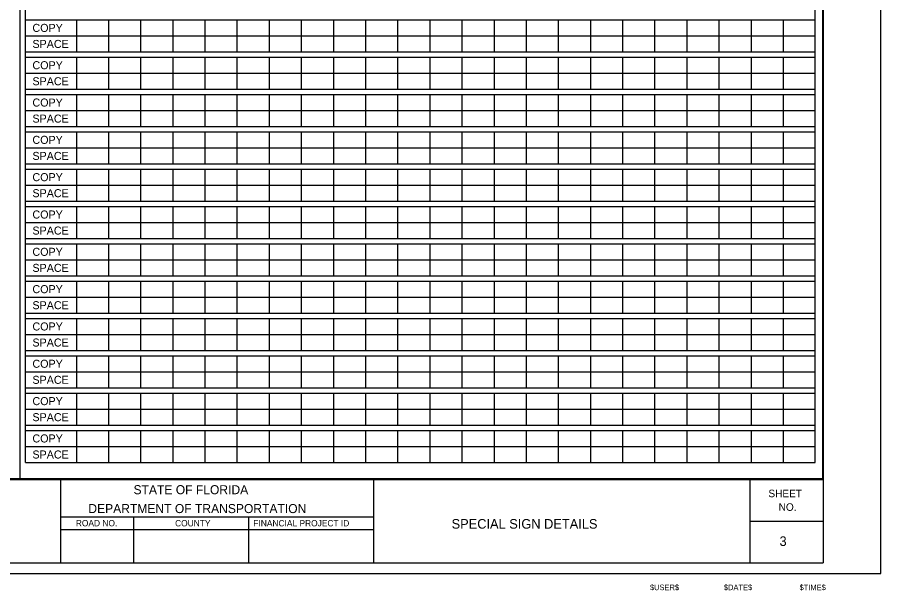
# Model space of a CAD drawing. Extents: x 17890459 to 17890580, y 17897938 to 17898017.
# Drawn here: x 17890519.4 to 17890580, y 17897938.3 to 17897978.6 of the extents above; entities that cross this region are included whole.
import ezdxf

# ---------------------------------------------------------------- set-up
doc = ezdxf.new("R2010")
doc.units = 0
for name, color, linetype in [('PlotBorder_dp', 7, 'Continuous'), ('SheetBorder_dp', 7, 'Continuous'), ('SheetLines_dp', 7, 'Continuous'), ('SheetLinesMisc2_dp', 7, 'Continuous'), ('TextMinor', 7, 'Continuous'), ('TextMisc', 7, 'Continuous')]:
    doc.layers.add(name, color=color, linetype=linetype)

msp = doc.modelspace()

# ---------------------------------------------------------------- linework, layer by layer
at = {"layer": 'PlotBorder_dp'}
msp.add_lwpolyline([(17890458.908, 17897939.544), (17890580.045, 17897939.544), (17890580.045, 17898017.365), (17890458.908, 17898017.365)], close=True, dxfattribs=at)
at = {"layer": 'SheetBorder_dp'}
for p, q in [((17890576.007, 17898016.631), (17890576.007, 17897940.278)), ((17890462.946, 17897946.151), (17890576.007, 17897946.151)), ((17890462.946, 17897940.278), (17890576.007, 17897940.278))]:
    msp.add_line(p, q, dxfattribs=at)
at = {"layer": 'SheetLines_dp'}
for p, q in [((17890522.413, 17897946.151), (17890522.413, 17897940.278)), ((17890544.438, 17897940.278), (17890544.438, 17897946.151)), ((17890570.867, 17897940.278), (17890570.867, 17897946.151)), ((17890522.413, 17897943.508), (17890544.438, 17897943.508)), ((17890527.552, 17897943.508), (17890527.552, 17897940.278)), ((17890535.628, 17897943.508), (17890535.628, 17897940.278)), ((17890570.867, 17897943.215), (17890576.007, 17897943.215)), ((17890522.413, 17897942.627), (17890544.438, 17897942.627))]:
    msp.add_line(p, q, dxfattribs=at)
at = {"layer": 'SheetLinesMisc2_dp'}
for p, q in [((17890519.566, 17898016.456), (17890519.566, 17897946.221)), ((17890575.98, 17897946.221), (17890575.98, 17898016.456)), ((17890519.957, 17897947.331), (17890519.957, 17897991.536)), ((17890575.447, 17897947.331), (17890575.447, 17897991.536)), ((17890519.957, 17897978.426), (17890575.447, 17897978.426)), ((17890523.529, 17897978.426), (17890523.529, 17897976.172)), ((17890525.787, 17897978.426), (17890525.787, 17897976.172)), ((17890528.044, 17897978.426), (17890528.044, 17897976.172)), ((17890530.301, 17897978.426), (17890530.301, 17897976.172)), ((17890532.558, 17897978.426), (17890532.558, 17897976.172)), ((17890534.815, 17897978.426), (17890534.815, 17897976.172)), ((17890537.073, 17897978.426), (17890537.073, 17897976.172)), ((17890539.33, 17897978.426), (17890539.33, 17897976.172)), ((17890541.587, 17897978.426), (17890541.587, 17897976.172)), ((17890543.844, 17897978.426), (17890543.844, 17897976.172)), ((17890546.102, 17897978.426), (17890546.102, 17897976.172)), ((17890548.359, 17897978.426), (17890548.359, 17897976.172)), ((17890550.617, 17897978.426), (17890550.617, 17897976.172)), ((17890552.874, 17897978.426), (17890552.874, 17897976.172)), ((17890555.132, 17897978.426), (17890555.132, 17897976.172)), ((17890557.388, 17897978.426), (17890557.388, 17897976.172)), ((17890559.646, 17897978.426), (17890559.646, 17897976.172)), ((17890561.903, 17897978.426), (17890561.903, 17897976.172)), ((17890564.161, 17897978.426), (17890564.161, 17897976.172)), ((17890566.418, 17897978.426), (17890566.418, 17897976.172)), ((17890568.675, 17897978.426), (17890568.675, 17897976.172)), ((17890570.932, 17897978.426), (17890570.932, 17897976.172)), ((17890573.19, 17897978.426), (17890573.19, 17897976.172)), ((17890519.957, 17897977.299), (17890575.447, 17897977.299)), ((17890519.957, 17897976.172), (17890575.447, 17897976.172)), ((17890519.957, 17897975.804), (17890575.447, 17897975.804)), ((17890523.529, 17897975.804), (17890523.529, 17897973.55)), ((17890525.787, 17897975.804), (17890525.787, 17897973.55)), ((17890528.044, 17897975.804), (17890528.044, 17897973.55)), ((17890530.301, 17897975.804), (17890530.301, 17897973.55)), ((17890532.558, 17897975.804), (17890532.558, 17897973.55)), ((17890534.815, 17897975.804), (17890534.815, 17897973.55)), ((17890537.073, 17897975.804), (17890537.073, 17897973.55)), ((17890539.33, 17897975.804), (17890539.33, 17897973.55)), ((17890541.587, 17897975.804), (17890541.587, 17897973.55)), ((17890543.844, 17897975.804), (17890543.844, 17897973.55)), ((17890546.102, 17897975.804), (17890546.102, 17897973.55)), ((17890548.359, 17897975.804), (17890548.359, 17897973.55)), ((17890550.617, 17897975.804), (17890550.617, 17897973.55)), ((17890552.874, 17897975.804), (17890552.874, 17897973.55)), ((17890555.132, 17897975.804), (17890555.132, 17897973.55)), ((17890557.388, 17897975.804), (17890557.388, 17897973.55)), ((17890559.646, 17897975.804), (17890559.646, 17897973.55)), ((17890561.903, 17897975.804), (17890561.903, 17897973.55)), ((17890564.161, 17897975.804), (17890564.161, 17897973.55)), ((17890566.418, 17897975.804), (17890566.418, 17897973.55)), ((17890568.675, 17897975.804), (17890568.675, 17897973.55)), ((17890570.932, 17897975.804), (17890570.932, 17897973.55)), ((17890573.19, 17897975.804), (17890573.19, 17897973.55)), ((17890519.957, 17897974.677), (17890575.447, 17897974.677)), ((17890519.957, 17897973.55), (17890575.447, 17897973.55)), ((17890519.957, 17897973.182), (17890575.447, 17897973.182)), ((17890523.529, 17897973.182), (17890523.529, 17897970.928)), ((17890525.787, 17897973.182), (17890525.787, 17897970.928)), ((17890528.044, 17897973.182), (17890528.044, 17897970.928)), ((17890530.301, 17897973.182), (17890530.301, 17897970.928)), ((17890532.558, 17897973.182), (17890532.558, 17897970.928)), ((17890534.815, 17897973.182), (17890534.815, 17897970.928)), ((17890537.073, 17897973.182), (17890537.073, 17897970.928)), ((17890539.33, 17897973.182), (17890539.33, 17897970.928)), ((17890541.587, 17897973.182), (17890541.587, 17897970.928)), ((17890543.844, 17897973.182), (17890543.844, 17897970.928)), ((17890546.102, 17897973.182), (17890546.102, 17897970.928)), ((17890548.359, 17897973.182), (17890548.359, 17897970.928)), ((17890550.617, 17897973.182), (17890550.617, 17897970.928)), ((17890552.874, 17897973.182), (17890552.874, 17897970.928)), ((17890555.132, 17897973.182), (17890555.132, 17897970.928)), ((17890557.388, 17897973.182), (17890557.388, 17897970.928)), ((17890559.646, 17897973.182), (17890559.646, 17897970.928)), ((17890561.903, 17897973.182), (17890561.903, 17897970.928)), ((17890564.161, 17897973.182), (17890564.161, 17897970.928)), ((17890566.418, 17897973.182), (17890566.418, 17897970.928)), ((17890568.675, 17897973.182), (17890568.675, 17897970.928)), ((17890570.932, 17897973.182), (17890570.932, 17897970.928)), ((17890573.19, 17897973.182), (17890573.19, 17897970.928)), ((17890519.957, 17897972.055), (17890575.447, 17897972.055)), ((17890519.957, 17897970.928), (17890575.447, 17897970.928)), ((17890519.957, 17897970.56), (17890575.447, 17897970.56)), ((17890523.529, 17897970.56), (17890523.529, 17897968.306)), ((17890525.787, 17897970.56), (17890525.787, 17897968.306)), ((17890528.044, 17897970.56), (17890528.044, 17897968.306)), ((17890530.301, 17897970.56), (17890530.301, 17897968.306)), ((17890532.558, 17897970.56), (17890532.558, 17897968.306)), ((17890534.815, 17897970.56), (17890534.815, 17897968.306)), ((17890537.073, 17897970.56), (17890537.073, 17897968.306)), ((17890539.33, 17897970.56), (17890539.33, 17897968.306)), ((17890541.587, 17897970.56), (17890541.587, 17897968.306)), ((17890543.844, 17897970.56), (17890543.844, 17897968.306)), ((17890546.102, 17897970.56), (17890546.102, 17897968.306)), ((17890548.359, 17897970.56), (17890548.359, 17897968.306)), ((17890550.617, 17897970.56), (17890550.617, 17897968.306)), ((17890552.874, 17897970.56), (17890552.874, 17897968.306)), ((17890555.132, 17897970.56), (17890555.132, 17897968.306)), ((17890557.388, 17897970.56), (17890557.388, 17897968.306)), ((17890559.646, 17897970.56), (17890559.646, 17897968.306)), ((17890561.903, 17897970.56), (17890561.903, 17897968.306)), ((17890564.161, 17897970.56), (17890564.161, 17897968.306)), ((17890566.418, 17897970.56), (17890566.418, 17897968.306)), ((17890568.675, 17897970.56), (17890568.675, 17897968.306)), ((17890570.932, 17897970.56), (17890570.932, 17897968.306)), ((17890573.19, 17897970.56), (17890573.19, 17897968.306)), ((17890519.957, 17897969.434), (17890575.447, 17897969.434)), ((17890519.957, 17897968.306), (17890575.447, 17897968.306)), ((17890519.957, 17897967.939), (17890575.447, 17897967.939)), ((17890523.529, 17897967.939), (17890523.529, 17897965.685)), ((17890525.787, 17897967.939), (17890525.787, 17897965.685)), ((17890528.044, 17897967.939), (17890528.044, 17897965.685)), ((17890530.301, 17897967.939), (17890530.301, 17897965.685)), ((17890532.558, 17897967.939), (17890532.558, 17897965.685)), ((17890534.815, 17897967.939), (17890534.815, 17897965.685)), ((17890537.073, 17897967.939), (17890537.073, 17897965.685)), ((17890539.33, 17897967.939), (17890539.33, 17897965.685)), ((17890541.587, 17897967.939), (17890541.587, 17897965.685)), ((17890543.844, 17897967.939), (17890543.844, 17897965.685)), ((17890546.102, 17897967.939), (17890546.102, 17897965.685)), ((17890548.359, 17897967.939), (17890548.359, 17897965.685)), ((17890550.617, 17897967.939), (17890550.617, 17897965.685)), ((17890552.874, 17897967.939), (17890552.874, 17897965.685)), ((17890555.132, 17897967.939), (17890555.132, 17897965.685)), ((17890557.388, 17897967.939), (17890557.388, 17897965.685)), ((17890559.646, 17897967.939), (17890559.646, 17897965.685)), ((17890561.903, 17897967.939), (17890561.903, 17897965.685)), ((17890564.161, 17897967.939), (17890564.161, 17897965.685)), ((17890566.418, 17897967.939), (17890566.418, 17897965.685)), ((17890568.675, 17897967.939), (17890568.675, 17897965.685)), ((17890570.932, 17897967.939), (17890570.932, 17897965.685)), ((17890573.19, 17897967.939), (17890573.19, 17897965.685)), ((17890519.957, 17897966.811), (17890575.447, 17897966.812)), ((17890519.957, 17897965.685), (17890575.447, 17897965.685)), ((17890519.957, 17897965.317), (17890575.447, 17897965.317)), ((17890523.529, 17897965.317), (17890523.529, 17897963.063)), ((17890525.787, 17897965.317), (17890525.787, 17897963.063)), ((17890528.044, 17897965.317), (17890528.044, 17897963.063)), ((17890530.301, 17897965.317), (17890530.301, 17897963.063)), ((17890532.558, 17897965.317), (17890532.558, 17897963.063)), ((17890534.815, 17897965.317), (17890534.815, 17897963.063)), ((17890537.073, 17897965.317), (17890537.073, 17897963.063)), ((17890539.33, 17897965.317), (17890539.33, 17897963.063)), ((17890541.587, 17897965.317), (17890541.587, 17897963.063)), ((17890543.844, 17897965.317), (17890543.844, 17897963.063)), ((17890546.102, 17897965.317), (17890546.102, 17897963.063)), ((17890548.359, 17897965.317), (17890548.359, 17897963.063)), ((17890550.617, 17897965.317), (17890550.617, 17897963.063)), ((17890552.874, 17897965.317), (17890552.874, 17897963.063)), ((17890555.132, 17897965.317), (17890555.132, 17897963.063)), ((17890557.388, 17897965.317), (17890557.388, 17897963.063)), ((17890559.646, 17897965.317), (17890559.646, 17897963.063)), ((17890561.903, 17897965.317), (17890561.903, 17897963.063)), ((17890564.161, 17897965.317), (17890564.161, 17897963.063)), ((17890566.418, 17897965.317), (17890566.418, 17897963.063)), ((17890568.675, 17897965.317), (17890568.675, 17897963.063)), ((17890570.932, 17897965.317), (17890570.932, 17897963.063)), ((17890573.19, 17897965.317), (17890573.19, 17897963.063)), ((17890519.957, 17897964.189), (17890575.447, 17897964.189)), ((17890519.957, 17897963.063), (17890575.447, 17897963.063)), ((17890519.957, 17897962.695), (17890575.447, 17897962.695)), ((17890523.529, 17897962.695), (17890523.529, 17897960.44)), ((17890525.787, 17897962.695), (17890525.787, 17897960.44)), ((17890528.044, 17897962.695), (17890528.044, 17897960.44)), ((17890530.301, 17897962.695), (17890530.301, 17897960.44)), ((17890532.558, 17897962.695), (17890532.558, 17897960.44)), ((17890534.815, 17897962.695), (17890534.815, 17897960.44)), ((17890537.073, 17897962.695), (17890537.073, 17897960.44)), ((17890539.33, 17897962.695), (17890539.33, 17897960.44)), ((17890541.587, 17897962.695), (17890541.587, 17897960.44)), ((17890543.844, 17897962.695), (17890543.844, 17897960.44)), ((17890546.102, 17897962.695), (17890546.102, 17897960.44)), ((17890548.359, 17897962.695), (17890548.359, 17897960.44)), ((17890550.617, 17897962.695), (17890550.617, 17897960.44)), ((17890552.874, 17897962.695), (17890552.874, 17897960.44)), ((17890555.132, 17897962.695), (17890555.132, 17897960.44)), ((17890557.388, 17897962.695), (17890557.388, 17897960.44)), ((17890559.646, 17897962.695), (17890559.646, 17897960.44)), ((17890561.903, 17897962.695), (17890561.903, 17897960.44)), ((17890564.161, 17897962.695), (17890564.161, 17897960.44)), ((17890566.418, 17897962.695), (17890566.418, 17897960.44)), ((17890568.675, 17897962.695), (17890568.675, 17897960.44)), ((17890570.932, 17897962.695), (17890570.932, 17897960.44)), ((17890573.19, 17897962.695), (17890573.19, 17897960.44)), ((17890519.957, 17897961.568), (17890575.447, 17897961.568)), ((17890519.957, 17897960.44), (17890575.447, 17897960.44)), ((17890519.957, 17897960.073), (17890575.447, 17897960.073)), ((17890523.529, 17897960.073), (17890523.529, 17897957.819)), ((17890525.787, 17897960.073), (17890525.787, 17897957.819)), ((17890528.044, 17897960.073), (17890528.044, 17897957.819)), ((17890530.301, 17897960.073), (17890530.301, 17897957.819)), ((17890532.558, 17897960.073), (17890532.558, 17897957.819)), ((17890534.815, 17897960.073), (17890534.815, 17897957.819)), ((17890537.073, 17897960.073), (17890537.073, 17897957.819)), ((17890539.33, 17897960.073), (17890539.33, 17897957.819)), ((17890541.587, 17897960.073), (17890541.587, 17897957.819)), ((17890543.844, 17897960.073), (17890543.844, 17897957.819)), ((17890546.102, 17897960.073), (17890546.102, 17897957.819)), ((17890548.359, 17897960.073), (17890548.359, 17897957.819)), ((17890550.617, 17897960.073), (17890550.617, 17897957.819)), ((17890552.874, 17897960.073), (17890552.874, 17897957.819)), ((17890555.132, 17897960.073), (17890555.132, 17897957.819)), ((17890557.388, 17897960.073), (17890557.388, 17897957.819)), ((17890559.646, 17897960.073), (17890559.646, 17897957.819)), ((17890561.903, 17897960.073), (17890561.903, 17897957.819)), ((17890564.161, 17897960.073), (17890564.161, 17897957.819)), ((17890566.418, 17897960.073), (17890566.418, 17897957.819)), ((17890568.675, 17897960.073), (17890568.675, 17897957.819)), ((17890570.932, 17897960.073), (17890570.932, 17897957.819)), ((17890573.19, 17897960.073), (17890573.19, 17897957.819)), ((17890519.957, 17897958.946), (17890575.447, 17897958.946)), ((17890519.957, 17897957.819), (17890575.447, 17897957.819)), ((17890519.957, 17897957.451), (17890575.447, 17897957.451)), ((17890523.529, 17897957.451), (17890523.529, 17897955.197)), ((17890525.787, 17897957.451), (17890525.787, 17897955.197)), ((17890528.044, 17897957.451), (17890528.044, 17897955.197)), ((17890530.301, 17897957.451), (17890530.301, 17897955.197)), ((17890532.558, 17897957.451), (17890532.558, 17897955.197)), ((17890534.815, 17897957.451), (17890534.815, 17897955.197)), ((17890537.073, 17897957.451), (17890537.073, 17897955.197)), ((17890539.33, 17897957.451), (17890539.33, 17897955.197)), ((17890541.587, 17897957.451), (17890541.587, 17897955.197)), ((17890543.844, 17897957.451), (17890543.844, 17897955.197)), ((17890546.102, 17897957.451), (17890546.102, 17897955.197)), ((17890548.359, 17897957.451), (17890548.359, 17897955.197)), ((17890550.617, 17897957.451), (17890550.617, 17897955.197)), ((17890552.874, 17897957.451), (17890552.874, 17897955.197)), ((17890555.132, 17897957.451), (17890555.132, 17897955.197)), ((17890557.388, 17897957.451), (17890557.388, 17897955.197)), ((17890559.646, 17897957.451), (17890559.646, 17897955.197)), ((17890561.903, 17897957.451), (17890561.903, 17897955.197)), ((17890564.161, 17897957.451), (17890564.161, 17897955.197)), ((17890566.418, 17897957.451), (17890566.418, 17897955.197)), ((17890568.675, 17897957.451), (17890568.675, 17897955.197)), ((17890570.932, 17897957.451), (17890570.932, 17897955.197)), ((17890573.19, 17897957.451), (17890573.19, 17897955.197)), ((17890519.957, 17897956.324), (17890575.447, 17897956.324)), ((17890519.957, 17897955.197), (17890575.447, 17897955.197)), ((17890519.957, 17897954.829), (17890575.447, 17897954.829)), ((17890523.529, 17897954.829), (17890523.529, 17897952.575)), ((17890525.787, 17897954.829), (17890525.787, 17897952.575)), ((17890528.044, 17897954.829), (17890528.044, 17897952.575)), ((17890530.301, 17897954.829), (17890530.301, 17897952.575)), ((17890532.558, 17897954.829), (17890532.558, 17897952.575)), ((17890534.815, 17897954.829), (17890534.815, 17897952.575)), ((17890537.073, 17897954.829), (17890537.073, 17897952.575)), ((17890539.33, 17897954.829), (17890539.33, 17897952.575)), ((17890541.587, 17897954.829), (17890541.587, 17897952.575)), ((17890543.844, 17897954.829), (17890543.844, 17897952.575)), ((17890546.102, 17897954.829), (17890546.102, 17897952.575)), ((17890548.359, 17897954.829), (17890548.359, 17897952.575)), ((17890550.617, 17897954.829), (17890550.617, 17897952.575)), ((17890552.874, 17897954.829), (17890552.874, 17897952.575)), ((17890555.132, 17897954.829), (17890555.132, 17897952.575)), ((17890557.388, 17897954.829), (17890557.388, 17897952.575)), ((17890559.646, 17897954.829), (17890559.646, 17897952.575)), ((17890561.903, 17897954.829), (17890561.903, 17897952.575)), ((17890564.161, 17897954.829), (17890564.161, 17897952.575)), ((17890566.418, 17897954.829), (17890566.418, 17897952.575)), ((17890568.675, 17897954.829), (17890568.675, 17897952.575)), ((17890570.932, 17897954.829), (17890570.932, 17897952.575)), ((17890573.19, 17897954.829), (17890573.19, 17897952.575)), ((17890519.957, 17897953.702), (17890575.447, 17897953.702)), ((17890519.957, 17897952.575), (17890575.447, 17897952.575)), ((17890519.957, 17897952.208), (17890575.447, 17897952.208)), ((17890523.529, 17897952.208), (17890523.529, 17897949.953)), ((17890525.787, 17897952.208), (17890525.787, 17897949.953)), ((17890528.044, 17897952.208), (17890528.044, 17897949.953)), ((17890530.301, 17897952.208), (17890530.301, 17897949.953)), ((17890532.558, 17897952.208), (17890532.558, 17897949.953)), ((17890534.815, 17897952.208), (17890534.815, 17897949.953)), ((17890537.073, 17897952.208), (17890537.073, 17897949.953)), ((17890539.33, 17897952.208), (17890539.33, 17897949.953)), ((17890541.587, 17897952.208), (17890541.587, 17897949.953)), ((17890543.844, 17897952.208), (17890543.844, 17897949.953)), ((17890546.102, 17897952.208), (17890546.102, 17897949.953)), ((17890548.359, 17897952.208), (17890548.359, 17897949.953)), ((17890550.617, 17897952.208), (17890550.617, 17897949.953)), ((17890552.874, 17897952.208), (17890552.874, 17897949.953)), ((17890555.132, 17897952.208), (17890555.132, 17897949.953)), ((17890557.388, 17897952.208), (17890557.388, 17897949.953)), ((17890559.646, 17897952.208), (17890559.646, 17897949.953)), ((17890561.903, 17897952.208), (17890561.903, 17897949.953)), ((17890564.161, 17897952.208), (17890564.161, 17897949.953)), ((17890566.418, 17897952.208), (17890566.418, 17897949.953)), ((17890568.675, 17897952.208), (17890568.675, 17897949.953)), ((17890570.932, 17897952.208), (17890570.932, 17897949.953)), ((17890573.19, 17897952.208), (17890573.19, 17897949.953)), ((17890519.957, 17897951.08), (17890575.447, 17897951.08)), ((17890519.957, 17897949.953), (17890575.447, 17897949.953)), ((17890519.957, 17897949.586), (17890575.447, 17897949.586)), ((17890523.529, 17897949.586), (17890523.529, 17897947.331)), ((17890525.787, 17897949.586), (17890525.787, 17897947.331)), ((17890528.044, 17897949.586), (17890528.044, 17897947.331)), ((17890530.301, 17897949.586), (17890530.301, 17897947.331)), ((17890532.558, 17897949.586), (17890532.558, 17897947.331)), ((17890534.815, 17897949.586), (17890534.815, 17897947.331)), ((17890537.073, 17897949.586), (17890537.073, 17897947.331)), ((17890539.33, 17897949.586), (17890539.33, 17897947.331)), ((17890541.587, 17897949.586), (17890541.587, 17897947.331)), ((17890543.844, 17897949.586), (17890543.844, 17897947.331)), ((17890546.102, 17897949.586), (17890546.102, 17897947.331)), ((17890548.359, 17897949.586), (17890548.359, 17897947.331)), ((17890550.617, 17897949.586), (17890550.617, 17897947.331)), ((17890552.874, 17897949.586), (17890552.874, 17897947.331)), ((17890555.132, 17897949.586), (17890555.132, 17897947.331)), ((17890557.388, 17897949.586), (17890557.388, 17897947.331)), ((17890559.646, 17897949.586), (17890559.646, 17897947.331)), ((17890561.903, 17897949.586), (17890561.903, 17897947.331)), ((17890564.161, 17897949.586), (17890564.161, 17897947.331)), ((17890566.418, 17897949.586), (17890566.418, 17897947.331)), ((17890568.675, 17897949.586), (17890568.675, 17897947.331)), ((17890570.932, 17897949.586), (17890570.932, 17897947.331)), ((17890573.19, 17897949.586), (17890573.19, 17897947.331)), ((17890519.957, 17897948.458), (17890575.447, 17897948.458)), ((17890519.957, 17897947.331), (17890575.447, 17897947.331)), ((17890463.151, 17897946.221), (17890575.98, 17897946.221))]:
    msp.add_line(p, q, dxfattribs=at)

# ---------------------------------------------------------------- texts
at = {"layer": 'TextMinor'}
for s, p in [('COPY', (17890520.444, 17897977.583)), ('SPACE', (17890520.444, 17897976.456)), ('COPY', (17890520.444, 17897974.961)), ('SPACE', (17890520.444, 17897973.834)), ('COPY', (17890520.444, 17897972.339)), ('SPACE', (17890520.444, 17897971.211)), ('COPY', (17890520.444, 17897969.718)), ('SPACE', (17890520.444, 17897968.59)), ('COPY', (17890520.444, 17897967.098)), ('SPACE', (17890520.444, 17897965.971)), ('COPY', (17890520.444, 17897964.474)), ('SPACE', (17890520.444, 17897963.346)), ('COPY', (17890520.444, 17897961.852)), ('SPACE', (17890520.444, 17897960.725)), ('COPY', (17890520.444, 17897959.23)), ('SPACE', (17890520.444, 17897958.102)), ('COPY', (17890520.444, 17897956.609)), ('SPACE', (17890520.444, 17897955.481)), ('COPY', (17890520.444, 17897953.989)), ('SPACE', (17890520.444, 17897952.861)), ('COPY', (17890520.444, 17897951.364)), ('SPACE', (17890520.444, 17897950.237)), ('COPY', (17890520.444, 17897948.743)), ('SPACE', (17890520.444, 17897947.615))]:
    msp.add_text(s, height=0.5625, dxfattribs=at).set_placement(p)
at = {"layer": 'TextMisc'}
for s, height, p in [('STATE OF FLORIDA', 0.63432, (17890527.544, 17897945.107)), ('DEPARTMENT OF TRANSPORTATION', 0.63432, (17890524.371, 17897943.781)), ('ROAD NO.', 0.4405, (17890523.492, 17897942.855)), ('COUNTY', 0.4405, (17890530.467, 17897942.848)), ('FINANCIAL PROJECT ID', 0.4405, (17890535.965, 17897942.848)), ('SPECIAL SIGN DETAILS', 0.67274, (17890549.894, 17897942.688)), ('3', 0.673, (17890572.933, 17897941.471)), ('$USER$', 0.3937, (17890563.829, 17897938.366)), ('$DATE$', 0.3937, (17890569.023, 17897938.366)), ('$TIME$', 0.3937, (17890574.34, 17897938.366))]:
    msp.add_text(s, height=height, dxfattribs=at).set_placement(p)
for s, p in [('SHEET', (17890572.152, 17897944.896)), ('NO.', (17890572.872, 17897943.941))]:
    msp.add_text(s, height=0.5286, rotation=359.86066, dxfattribs=at).set_placement(p)

doc.saveas('drawing.dxf')
